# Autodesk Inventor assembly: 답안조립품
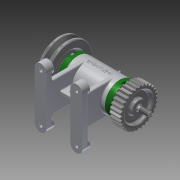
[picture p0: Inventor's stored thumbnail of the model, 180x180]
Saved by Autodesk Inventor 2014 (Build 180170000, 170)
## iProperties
Created: 2015-11
Part Number: 답안조립품
Document SubType Name: Assembly
Designer: Owner
Author: Owner
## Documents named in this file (13)
- C:\Documents and Settings\Owner\바탕 화면\451109V1020\답안조립품.iam
- C:\Documents and Settings\Owner\바탕 화면\451109V1020\본체.ipt
- C:\Documents and Settings\Owner\바탕 화면\451109V1020\커버.ipt
- C:\Documents and Settings\Owner\바탕 화면\451109V1020\베어링 15 x 32 x 9.ipt
- C:\Documents and Settings\Owner\바탕 화면\451109V1020\축.ipt
- C:\Documents and Settings\Owner\바탕 화면\451109V1020\오일 실 15 25 7.ipt
- C:\Documents and Settings\Owner\바탕 화면\451109V1020\볼트 M4 x 12.ipt
- C:\Documents and Settings\Owner\바탕 화면\451109V1020\V벨트풀리.ipt
- C:\Documents and Settings\Owner\바탕 화면\451109V1020\스퍼기어.ipt
- C:\Documents and Settings\Owner\바탕 화면\451109V1020\와셔 6x11.5.ipt
- C:\Documents and Settings\Owner\바탕 화면\451109V1020\스프링와셔 8.ipt
- C:\Documents and Settings\Owner\바탕 화면\451109V1020\너트 M 8.ipt
- C:\Documents and Settings\Owner\바탕 화면\451109V1020\니플 M 6 x 0.75.ipt
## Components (15 placed, 3 different names)
1. KS B 2023 6002 - 15 x 32 x 9:1
2. KS B 2023 6002 - 15 x 32 x 9:2
3. ISO 4762 M4 x 12:5
4. ISO 4762 M4 x 12:6
5. ISO 4762 M4 x 12:7
6. ISO 4762 M4 x 12:8
7. ISO 4762 M4 x 12:9
8. ISO 4762 M4 x 12:10
9. ISO 4762 M4 x 12:11
10. ISO 4762 M4 x 12:12
11. V벨트풀리:1
12. ISO 4762 M4 x 12:1
13. ISO 4762 M4 x 12:2
14. ISO 4762 M4 x 12:3
15. ISO 4762 M4 x 12:4
